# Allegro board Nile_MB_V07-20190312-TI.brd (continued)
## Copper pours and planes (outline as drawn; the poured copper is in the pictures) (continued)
GND on TOP (solid shape): 80.77,15.3 80.05,15.3 80.05,36.26 80.77,36.26
GND on TOP (solid shape): 80.79,14.53 58.83,14.53 58.83,15.27 80.79,15.27
GND on TOP (solid shape): 81.36,37.76 78.46,37.76 78.46,38.46 81.36,38.46
GND on TOP (solid shape): 81.86,30.41 81.16,30.41 81.16,38.46 81.86,38.46
GND on TOP (solid shape): 91.56,29.71 81.16,29.71 81.16,30.41 91.56,30.41
GND on TOP (solid shape): 92.26,45.66 78.46,45.66 78.46,46.36 92.26,46.36
GND on TOP (solid shape): 92.26,29.71 91.56,29.71 91.56,45.66 92.26,45.66
GND on TOP (solid shape): 76.6,28.97 76.47,28.84 76.47,27.89 75.93,27.89 75.93,29.48 76.6,29.48
GND on TOP (solid shape): 72.22,30.3 72.41,30.11 72.73,30.11 72.73,29.67 71.97,29.67 71.97,29.55 71.33,29.55 71.33,29.98 71.46,29.98 71.72,30.25 71.72,30.94 72.22,30.94
GND on BOTTOM (solid shape): 5.78,10.33 5.03,10.33 5.03,42.28 5.78,42.28
GND on BOTTOM (solid shape): 20.61,7.2 19.87,7.2 19.87,16.23 20.61,16.23
GND on BOTTOM (solid shape): 27.3,20.72 26.73,20.72 26.73,32.07 27.3,32.07
GND on BOTTOM (solid shape): 31.71,9.54 30.89,9.54 30.89,16.62 31.71,16.62
GND on BOTTOM (solid shape): 35,19.04 26.73,19.04 26.73,19.59 35,19.59
GND on BOTTOM (solid shape): 35.6,30.68 35.02,30.68 35.02,32.85 35.6,32.85
GND on BOTTOM (solid shape): 35.6,22.08 35.02,22.08 35.02,28.28 35.6,28.28
GND on BOTTOM (solid shape): 35.61,33.44 26.71,33.44 26.71,34.01 35.61,34.01
GND on BOTTOM (solid shape): 37.43,4.7 22.38,4.7 22.38,5.45 37.43,5.45
GND on BOTTOM (solid shape): 37.65,34.87 34.54,34.87 34.54,39.46 37.65,39.46
GND on BOTTOM (solid shape): 38.92,9.51 33.19,9.51 33.19,10.26 38.92,10.26
GND on BOTTOM (solid shape): 40.87,4.66 40.1,4.66 40.1,10.24 40.87,10.24
GND on BOTTOM (solid shape): 46.72,18.72 41.27,18.72 41.27,19.42 46.72,19.42
GND on BOTTOM (solid shape): 48.73,26.35 46.61,26.35 46.61,27.35 48.73,27.35
GND on BOTTOM (solid shape): 57.24,26.48 56.91,26.48 56.91,30.89 57.24,30.89
GND on BOTTOM (solid shape): 57.86,18.05 47.86,18.05 47.86,18.55 57.86,18.55
GND on BOTTOM (solid shape): 56.17,23.12 55.32,23.12 55.32,24.62 55.42,24.72 55.42,25.14 55.76,25.48 55.76,25.95 56.17,25.95
GND on BOTTOM (solid shape): 49.99,31.28 51.6,31.28 51.6,31.47 52.76,31.47 52.76,31.02 49.83,31.02 49.63,31.22 49.63,31.48 49.99,31.48
GND on BOTTOM (solid shape): 52.9,21.42 52.7,21.22 52.15,21.22 52.15,21.62 52,21.77 51.55,21.77 51.45,21.87 51.45,22.02 51.5,22.07 52.9,22.07
GND on BOTTOM (solid shape): 55.72,25.06 54.82,25.06 54.41,24.65 54.41,23.72 54.37,23.67 53.92,23.67 53.92,25.07 54.27,25.07 54.47,25.27 55.72,25.27
GND on BOTTOM (solid shape): 59.25,22.57 59.2,22.52 58.9,22.52 58.9,22.87 58.75,23.02 58.25,23.02 57.25,23.07 57.1,23.22 57.1,23.47 59.25,23.47
GND on BOTTOM (solid shape): 59.55,20.62 59.55,19.97 59.3,19.72 57.15,19.72 56.85,20.02 56.85,20.62 56.95,20.72 57.65,20.72 57.65,20.82 59.35,20.82
GND on BOTTOM (solid shape): 54.45,21.82 56.55,21.82 56.6,21.77 56.6,21.52 56.55,21.47 56.3,21.47 55.95,21.12 55.95,20.92 54.5,20.92 54.5,21.27 54.1,21.67 53.75,21.87 53.75,22.02 53.9,22.17 54.1,22.17
GND on BOTTOM (solid shape): 20.91,40.06 26.51,40.06 26.51,19.06 19.56,19.06 19.56,10.31 15.53,10.31 15.53,11.01 18.86,11.01 18.86,19.76 25.76,19.76 25.76,39.31 20.21,39.31 20.21,42.41 5.06,42.41 5.06,43.11 20.91,43.11
GND on INNER LAYER 7 (solid shape): 66.63,35.73 66.66,35.62 66.56,35.56 60.34,35.43 60.34,35.48 60.14,35.67 59.94,35.47 59.94,35.42 59.56,35.42 59.55,35.44 58.79,35.44 58.57,35.66 58.26,35.66 58.26,35.7 58.06,35.88 57.86,35.7 57.85,35.66 56.87,35.66 56.8,35.58 56.51,35.58 56.47,35.63 54.62,35.63 54.26,35.26 54.18,35.23 54.11,35.27 53.9,35.35 53.74,35.18 53.7,35.11 53.61,35.1 53.42,35.06 53.36,34.87 53.34,34.78 53.26,34.75 52.95,34.75 50.72,32.51 50.72,31.43 49.77,30.47 49.66,30.45 49.59,30.54 49.58,31.39 49.23,31.75 49.23,32.43 50.34,33.53 50.58,33.53 53.09,36.04 66.32,36.04
GND on INNER LAYER 7 (solid shape): outline of 706 points within 49.36,23.53 54.78,29.61
GND on INNER LAYER 9 (solid shape): 50.41,30.66 50.41,29.8 50.51,29.7 51.36,29.7 51.47,29.59 51.86,29.59 51.95,29.68 51.95,29.93 51.97,29.95 52.25,29.95 52.29,29.91 52.29,29.38 52.02,29.11 51.72,29.11 51.62,29.01 51.62,28.64 51.55,28.57 51.33,28.57 51.08,28.82 51.08,28.95 50.84,29.19 49.74,29.19 49.64,29.29 49.64,29.5 49.91,29.77 49.91,30.35 49.81,30.45 49.81,30.75 49.85,30.79 50.28,30.79
GND on TOP: outline of 146 points within 0.22,0.22 92.74,55.99 ; 12 cut-outs
GND on BOTTOM: outline of 146 points within 0.22,0.22 92.74,55.99 ; 15 cut-outs
GND on INNER LAYER 2: outline of 146 points within 0.22,0.22 92.74,55.99 ; 1 cut-out
GND on INNER LAYER 3: outline of 146 points within 0.22,0.22 92.74,55.99 ; 19 cut-outs
GND on INNER LAYER 4, INNER LAYER 9: outline of 146 points within 0.22,0.22 92.74,55.99
GND on INNER LAYER 5: outline of 146 points within 0.22,0.22 92.74,55.99 ; 7 cut-outs
GND on INNER LAYER 6: outline of 146 points within 0.22,0.22 92.74,55.99 ; 3 cut-outs
GND on INNER LAYER 7: outline of 146 points within 0.22,0.22 92.74,55.99 ; 1 cut-out
GND on INNER LAYER 8: outline of 146 points within 0.22,0.22 92.74,55.99 ; 5 cut-outs
V5P0_HUB on TOP (solid shape): 31.61,24.81 31.31,24.51 30.91,24.51 30.76,24.66 30.76,26.55 31.27,27.06 31.61,27.06
V5P0_HUB on INNER LAYER 3 (solid shape): 31.46,26.26 31.46,24.81 31.31,24.66 30.91,24.66 30.91,25.51 30.56,25.86 30.56,26.36 30.66,26.46 31.26,26.46
VBAT_EX on TOP (solid shape): 6.76,18.96 6.76,16.11 3.56,16.11 3.56,18.96 3.61,19.01 6.71,19.01
VBAT_EX on BOTTOM (solid shape): 66.32,15.11 66.32,14.55 66.18,14.41 64.79,14.41 64.79,15.17 64.99,15.37 66.06,15.37
VBAT_EX on BOTTOM (solid shape): 20.48,25.33 20.48,24.28 22.13,22.63 22.13,20.38 22.03,20.28 21.13,20.28 21.08,20.33 21.08,21.48 20.58,21.98 20.58,22.98 19.68,23.88 19.68,25.33 19.73,25.38 20.43,25.38
VBAT_EX on BOTTOM (solid shape): 45.44,37.4 45.44,35.29 45.19,35.04 44.25,35.04 43.5,34.29 42.8,34.29 42.8,35.31 43,35.51 43.87,35.51 44.15,35.79 44.15,36.14 44.24,36.23 44.53,36.23 44.73,36.43 44.73,37.47 45.37,37.47
VBAT_EX on BOTTOM (solid shape): 65.3,14.52 64.95,14.17 63.7,14.17 63.1,13.57 57.75,13.57 57.55,13.77 56.95,13.77 56.75,13.97 56.75,15.12 56.9,15.27 58.25,15.27 58.25,15.22 58.6,14.87 61.8,14.87 62.15,15.22 62.4,15.22 62.5,15.12 63.55,15.12 63.75,15.32 65.3,15.32
VBAT_EX on BOTTOM (solid shape): 57.38,16.83 57.38,14.03 57.18,13.83 56.74,13.83 56.18,13.27 56.18,12.88 54.22,11.39 49.54,11.32 42.65,13.48 40.53,13.48 40.48,13.43 40.33,13.43 40.18,13.58 40.18,15.78 40.28,15.88 43.56,15.88 45.04,14.95 50.36,13.36 51.23,13.2 53.59,13.12 55.35,14.04 55.5,14.14 55.5,14.37 55.47,14.87 55.53,15.54 55.55,15.77 55.58,16.31 55.87,17.02 57.18,17.03
VBAT_EX on INNER LAYER 3 (solid shape): outline of 316 points within 2.66,13.31 22.91,22.23
VBAT_EX on INNER LAYER 8 (solid shape): 43.75,34.42 43.74,32.57 42.69,32.57 42.69,34.61 43.47,34.66
VBAT_EX on INNER LAYER 8 (solid shape): 22.76,21.21 23.21,21.21 25.16,19.26 27.57,19.26 27.72,19.11 37.7,19.11 41.91,14.9 41.91,13.46 41.86,13.41 40.16,13.41 38.86,14.71 38.86,15.36 38.12,16.11 38.12,16.11 37.86,16.4 37.57,16.65 37.57,16.65 37.01,17.21 33.71,17.21 32.96,17.96 21.04,17.96 20.29,18.58 20.29,18.58 20.01,18.86 20.01,21.01 21.26,22.26 21.71,22.26
VBAT_EX on INNER LAYER 8 (solid shape): 61.15,15.39 61.22,15.35 61.24,15.27 61.5,14.94 61.76,15.27 61.78,15.35 61.86,15.39 66.59,15.39 66.63,15.35 67.24,15.35 67.48,15.11 67.48,14.14 67.33,13.98 65.65,13.98 65.39,14.24 65.05,14.24 64.73,13.92 64.7,13.92 64.34,13.93 64.3,13.58 64.3,13.47 64.21,13.42 56.57,13.42 56.28,13.95 56.28,13.99 56.22,14.05 56.15,14.17 56.1,14.18 56.02,14.25 55.25,14.25 54.58,14.31 54.58,15.09 54.64,15.15 56.39,15.15 56.56,15.14 56.7,15 56.7,14.9 57.24,14.36 57.87,14.36 58.05,14.54 59.3,14.54 59.33,14.47 59.35,14.44 59.69,14.38 59.8,14.71 59.76,14.78 60.37,15.39
VBAT_EX on INNER LAYER 9 (solid shape): 41.78,13.48 40.28,13.48 40.28,16.48 41.78,16.48
VBAT_EX on INNER LAYER 9 (solid shape): 43.63,32.43 42.63,32.43 42.63,34.73 43.63,34.73
VBAT_EX on INNER LAYER 9 (solid shape): 67.16,14.35 64.85,14.35 64.85,15.14 67.16,15.14
VBAT_EX on INNER LAYER 9 (solid shape): 22.11,22.06 22.11,21.66 22.56,21.21 23.11,21.21 23.86,20.46 23.86,19.91 24.76,19.01 34.56,19.01 34.56,18.26 34.21,17.91 31.26,17.91 31.16,18.01 23.16,18.01 21.21,19.96 21.21,22.21 21.26,22.26 21.91,22.26
VBATT on TOP (solid shape): 72.09,23 72.22,22.87 72.21,21.57 72.5,21.12 72.62,20.52 72.47,20.28 71.61,20.29 71.53,20.45 71.54,21.19 71.54,22.58 71.59,22.62 71.59,22.68 71.84,22.94 71.84,23.83 72.03,24.02 72.09,24.02
VBATT on BOTTOM (solid shape): 25.41,36.31 25.41,35.61 25.26,35.46 24.56,35.46 24.21,35.81 24.21,36.36 24.31,36.46 25.26,36.46
VBATT on BOTTOM (solid shape): 69.8,11.47 69.8,10.97 69.77,10.52 68.15,10.52 68.14,10.53 68.1,11.42 68.25,11.72 68.3,12.57 69.75,12.57
VBATT on BOTTOM (solid shape): 25.46,26.31 25.46,24.96 25.41,22.21 24.91,21.71 23.26,21.71 23.26,23.61 24.71,25.06 24.71,26.16 24.91,26.36 25.31,26.41
VBATT on BOTTOM (solid shape): 67.04,22.78 67.04,20.58 66.95,20.49 66.62,20.49 66.44,20.67 66.25,20.82 66.1,20.92 65.55,20.92 65.51,20.93 65.42,20.71 64.85,20.77 64.55,21.28 64.55,22.93 66.89,22.93
VBATT on INNER LAYER 8 (solid shape): 25.46,24.71 24.81,24.71 24.81,26.26 25.46,26.26
VBATT on INNER LAYER 8 (solid shape): 25.31,22.71 25.31,21.61 25.21,21.51 23.46,21.51 23.16,21.81 23.16,22.71 23.36,22.91 25.11,22.91
VBATT on INNER LAYER 8 (solid shape): outline of 906 points within 47.13,9.7 73.79,22.2
VBATT on INNER LAYER 9 (solid shape): 69.75,11.23 72.03,8.95 72.03,8.32 71.93,8.22 71.32,8.22 69.65,9.92 68.25,10.67 68.25,11.37 68.85,11.42 69.75,11.47
VBUS_OUT_5V on BOTTOM (solid shape): 10.16,41.61 10.16,40.01 9.96,39.81 8.01,39.81 7.96,39.86 7.96,41.71 10.06,41.71
VBUS_OUT_5V on BOTTOM (solid shape): 19.66,52.31 19.66,50.46 19.21,50.01 18.91,50.01 18.01,49.11 18.01,47.96 17.71,47.66 17.01,47.66 16.71,47.96 16.71,49.96 17.16,50.41 18.31,50.41 19.01,51.11 19.01,52.36 19.06,52.41 19.56,52.41
VBUS_OUT_5V on INNER LAYER 8 (solid shape): 10.16,41.66 10.16,40.46 9.51,39.81 7.96,39.81 7.96,41.71 10.11,41.71
VBUS_OUT_5V on INNER LAYER 8 (solid shape): 18.61,49.66 18.61,49.16 17.86,48.41 17.86,47.86 16.91,47.86 16.81,47.96 16.81,49.41 17.36,49.96 18.31,49.96
VDD13_BT on INNER LAYER 8 (solid shape): 23.7,9.57 23.7,8.77 23.5,8.57 23.5,7.82 23.4,7.72 21.4,7.72 21.3,7.82 21.3,8.42 23,8.42 23.15,8.57 23.15,8.82 23.23,9.01 23.15,9.2 23.15,9.37 23.45,9.67 23.6,9.67
VDD33_FEM on INNER LAYER 5 (solid shape): 24.4,12.71 24.4,12.19 24.38,12.18 24.3,12.02 24.38,11.86 24.4,11.84 24.4,11.15 24.26,11.01 24.2,10.78 24.28,10.56 24.39,10.46 24.4,9.38 24.29,9.3 24.15,9.03 24.25,8.75 24.33,8.7 24.4,8.67 24.8,8.27 28,8.27 28.8,9.07 28.8,9.12 29.02,9.33 29.02,10.18 28.8,10.39 28.8,10.42 27.95,11.27 27.95,11.72 28.05,11.82 28.85,11.82 29.67,11 29.67,8.53 27.8,6.67 27.5,6.67 27.49,6.69 27.25,6.83 27.02,6.69 27.01,6.67 25.56,6.67 25.5,6.73 24.83,6.73 24.78,6.68 24.4,6.68 23.9,7.18 23.89,7.18 23.35,7.72 23.35,9.83 23.38,9.86 23.4,9.91 23.5,10.02 23.5,10.15 23.6,10.24 23.6,11.39 23.57,11.42 23.57,11.99 23.5,12.05 23.5,12.17 23.09,12.58 23.09,13.13 23.21,13.26 23.85,13.26
VDD33_FEM on INNER LAYER 8 (solid shape): 24.65,7.62 24.59,7.56 24.59,7.18 24.81,6.96 24.81,6.67 24.53,6.39 24.53,6.2 24.26,6.2 24.16,6.3 24.16,6.71 24.29,6.84 24.29,7.05 23.89,7.45 23.89,7.97 23.99,8.07 24.65,8.07
VDD33_FEM on INNER LAYER 8 (solid shape): 26.97,9.64 27.03,9.64 27.14,9.53 27.14,8.28 27.07,8.21 27.06,8.21 26.84,8.02 26.95,7.77 26.94,7.6 26.81,7.51 26.66,7.53 26.47,7.71 26.38,7.78 26.36,7.81 26.36,8.2 26.59,8.43 26.6,8.43 26.67,8.64 26.7,8.85 26.7,8.99 26.71,8.99 26.72,9.16 26.79,9.32 26.7,9.48 26.7,9.56 26.81,9.67 26.94,9.67
VDD_CAP on BOTTOM (solid shape): 32.26,38.21 32.26,37.26 32.11,37.11 30.61,37.11 30.31,37.41 30.31,38.36 30.36,38.41 32.06,38.41
VDD_CAP on BOTTOM (solid shape): 46.96,34.71 46.96,33.99 46.77,33.8 46.39,33.8 46.1,33.51 46.1,32.93 45.83,32.66 45.26,32.66 45.18,32.74 45.18,34.23 45.51,34.56 45.51,34.91 46.76,34.91
VDD_CAP on BOTTOM (solid shape): 21.56,38.51 21.56,37.01 21.31,36.76 17.81,36.76 16.16,35.11 16.16,33.96 15.81,33.61 10.56,33.61 10.31,33.86 10.31,35.36 10.76,35.81 14.31,35.81 15.26,36.76 15.26,38.41 15.46,38.61 21.46,38.61
VDD_CAP on INNER LAYER 8 (solid shape): 32.36,38.61 32.36,37.26 32.06,36.96 30.46,36.96 29.26,38.16 24.79,38.16 24.72,38.24 22.64,38.24 21.54,37.14 21.54,37.06 17.81,37.06 17.61,37.26 17.61,38.61 17.66,38.66 20.16,38.66 21.46,39.96 31.01,39.96
VDD_CAP on INNER LAYER 8 (solid shape): outline of 150 points within 30.3,32.48 46.7,38.42
VDD_LCD_2P8 on BOTTOM (solid shape): 54.9,50.45 54.9,46.01 51.03,42.14 51.03,40.81 50.68,40.46 50.68,38.5 50.34,38.16 49.88,38.16 49.65,38.39 49.65,39.52 50.1,39.97 50.1,42.76 54.19,46.85 54.19,50.25 54.18,50.26 54.18,50.41 54.34,50.57 54.78,50.57
VIN_8V5 on BOTTOM (solid shape): 29.83,40.43 29.83,38.33 29.08,37.58 28.18,37.58 27.08,38.68 27.08,41.23 27.21,41.36 28.9,41.36
VIN_8V5 on INNER LAYER 8 (solid shape): 77.85,36.38 75.96,36.38 75.96,37.72 77.85,37.72
CAM2_VDD on BOTTOM (solid shape): 19.28,27.58 20.43,27.58 20.43,26.13 20.38,26.08 18.83,26.08 18.73,26.18 18.73,26.83 18.48,27.08 17.93,27.08 17.93,27.78 18.08,27.93 18.93,27.93
CAM2_VDD on INNER LAYER 8 (solid shape): 20.43,28.58 20.43,26.03 18.88,26.03 18.63,26.28 18.63,26.83 18.83,27.03 19.18,27.03 19.48,27.33 19.48,28.68 20.33,28.68
CAM_FRONT_1P8 on TOP (solid shape): 45.23,17.1 45.74,17.07 45.94,16.89 45.89,16.49 45.9,16.47 45.9,16.02 45.89,15.9 45.89,15.85 45.74,15.52 45.71,14.95 45.71,13.89 45.94,13.6 45.96,12.6 45.97,12.41 44.72,12.41 44.64,12.63 44.64,15.5 44.46,15.89 44.43,16.44 44.57,17.09 44.84,17.27
DC_5V on BOTTOM (solid shape): 74.19,47.73 74.19,45.17 73.73,44.71 72.71,44.71 72.28,44.28 72.28,44.27 71.85,43.84 71.84,43.84 71.8,43.8 71.8,42.33 71.7,42.23 68.28,42.23 67.94,42.57 67.94,44.43 68.28,44.77 70.25,44.77 70.58,45.1 70.58,45.81 72.71,47.94 73.98,47.94
DC_IN on BOTTOM (solid shape): 65.63,18.54 65.82,18.35 65.82,17.82 65.31,17.31 65.31,16.75 65.19,16.63 64.3,16.07 63.3,16.07 63.15,16.27 63.15,17.52 63.85,17.52 64,17.62 64.05,18.27 64.15,18.57 64.75,18.57
DC_IN on BOTTOM (solid shape): 72.15,41.42 72.15,38.17 72.5,37.82 72.5,33.62 72.25,33.37 71,33.37 70.7,33.67 70.7,35.02 70.75,35.07 71.35,35.07 71.55,35.27 71.55,36.72 71,37.27 70.6,37.27 70.5,37.37 70.5,38.02 70.35,38.17 68.2,38.17 68.15,38.22 68.15,39.32 69,39.32 69.5,39.82 69.5,40.52 69.15,40.87 69.15,41.12 69.8,41.77 71.8,41.77
DC_IN on INNER LAYER 9 (solid shape): 64.3,45.87 64.3,44.72 66.56,42.46 66.59,42.42 66.63,42.39 68.5,39.61 71.23,39.56 71.45,39.37 71.45,38.12 67.7,38.12 65.48,40.34 65.43,40.4 65.38,40.44 62.7,43.12 62.7,45.82 63.05,46.17 64,46.17
DC_IN on INNER LAYER 9 (solid shape): outline of 565 points within 63.44,15.34 82.83,39.32
SPK- on BOTTOM (solid shape): 68.68,6.02 68.68,5.64 69.18,5.14 69.6,5.14 69.6,4.32 69.58,4.3 69.05,4.3 68.89,4.46 68.89,4.7 68.56,5.03 67.89,5.03 67.63,5.29 67.63,5.72 68.01,6.1 68.6,6.1
USB_IN_MID on TOP (solid shape): 74.19,24.4 75.61,24.4 75.61,23.7 74.38,23.7 73.81,24.27 73.3,24.27 73.05,24.52 74.06,24.52
USB_IN_MID on TOP (solid shape): 76.13,23.75 76.36,23.75 76.64,23.47 76.65,22.22 76.74,21.67 76.66,21.63 76.54,21.59 76.39,21.62 76.33,21.62 76.26,21.63 76.02,21.7 75.97,23.06 75.36,23.67 75.36,24.07 75.53,24.24 75.64,24.24
USB_VBUS on TOP (solid shape): 75.13,25.08 75.58,25.08 75.76,25.08 76.21,25.08 76.22,25.07 76.35,25.02 76.4,25.02 76.5,24.92 76.6,24.72 76.9,24.47 77.25,24.17 77.55,23.87 77.87,23.87 79.3,23.82 79.55,23.57 79.55,22.82 77.84,22.86 76.93,22.86 76.76,23.03 76.76,23.54 76.68,23.62 76.68,23.63 76.5,23.81 76.41,23.81 76.4,23.83 76.21,23.83 75.69,24.34 75.69,24.47 75.58,24.47 75.39,24.66 73.8,24.68 73.64,24.74 73.33,24.72 73.14,24.86 73.14,25.03 73.67,25.04 73.94,25.01 74.15,25.12 75.13,25.12
V_LEDA on BOTTOM (solid shape): 36.64,42.11 36.64,40.24 36.61,40.21 35.62,40.21 35.49,40.34 35.49,40.89 35.12,41.26 34.34,41.26 34.35,41.26 34.21,41.26 34.19,41.28 34.19,42.17 34.38,42.36 36.39,42.36
V_LEDA on INNER LAYER 9 (solid shape): 42.08,50.39 42.08,48.68 39.86,46.46 39.86,42.76 38.42,41.32 34.31,41.32 34.09,41.54 34.09,42.57 34.56,42.91 34.96,42.91 37.51,42.81 37.61,42.86 37.86,43.11 38.01,43.56 38.21,43.96 38.26,46.91 41.63,50.49 41.98,50.49
VCOIN on INNER LAYER 9 (solid shape): 54.66,15.07 54.74,14.43 54.75,14.33 53.69,14.38 53.56,14.29 53.53,14.06 53.5,13.94 52.86,13.79 52.57,13.72 52.35,14.02 52.24,14.13 52.24,14.72 52.67,15.15 54.04,15.3 54.44,15.3
VCONN_IN on TOP (solid shape): 79.38,18.56 79.38,16.17 78.73,15.52 71.69,15.52 71.41,15.8 71.41,17.49 71.45,17.53 73.54,17.53 74.09,16.98 76.5,16.98 76.96,17.44 76.96,18.15 77.52,18.71 79.23,18.71
VCONN_IN on TOP (solid shape): 76.75,21.31 76.75,20.99 78.04,19.7 78.04,18.86 78.36,18.54 78.36,18.02 78.19,17.85 77.05,17.85 76.96,17.94 76.96,19.81 76.14,20.63 76.08,20.63 76.08,21.35 76.13,21.4 76.66,21.4
VCONN_IN on INNER LAYER 2 (solid shape): outline of 204 points within 70.01,16.08 73.78,23.42
VPH_PWR on TOP (solid shape): 68.66,27.7 68.66,26.94 68.54,26.94 68.41,27.06 68.41,27.38 67.97,27.83 67.58,27.83 67.58,28.33 68.03,28.33
VPH_PWR on TOP (solid shape): 67.91,26.96 67.91,25.9 68.09,25.72 68.09,25.31 68.05,25.27 67.42,25.27 67.36,25.33 67.36,26.88 67.57,27.09 67.78,27.09
VPH_PWR on TOP (solid shape): 72.6,23.13 73.3,22.43 73.77,22.43 74.38,21.81 74.38,20.46 73.62,20.46 73.62,20.46 72.35,21.72 72.35,23.95 72.47,24.08 72.6,24.08
VPH_PWR on TOP (solid shape): 68.55,24.24 68.55,23.38 68.37,23.2 68.33,23.2 68.25,23.12 68.25,22.84 68.13,22.72 67.69,22.72 67.35,23.06 67.35,24.21 67.46,24.32 68.47,24.32
VPH_PWR on TOP (solid shape): 74.41,21.77 74.41,20.47 74.4,20.46 74.4,20.2 75.02,19.58 75.01,19.06 75.22,18.92 76.02,18.94 76.35,18.83 76.38,17.75 76.32,17.22 75.55,17.18 74.89,17.19 74.28,17.19 74.09,17.38 74.09,17.56 73.48,18.17 73.01,18.17 72.87,18.31 72.87,18.79 73,18.92 73.54,18.92 73.76,19.14 73.76,19.81 73.49,20.08 73.06,20.08 73.01,20.13 73.01,21.59 72.89,21.71 73.2,22.02 74.16,22.02
VPH_PWR on BOTTOM (solid shape): 29.83,26.95 30.06,26.72 30.06,26.42 29.41,25.77 28.64,25.77 28.71,27.16 28.96,27.16
VPH_PWR on BOTTOM (solid shape): 30.05,24.19 30.05,23.93 29.7,23.58 29.68,23.57 28.66,23.57 28.66,24.82 29.43,24.82
VPH_PWR on BOTTOM (solid shape): 74.48,32.11 74.48,30.56 74.41,30.49 73.91,30.49 73.81,30.59 73.81,32.12 73.9,32.21 74.38,32.21
VPH_PWR on BOTTOM (solid shape): 23.52,17.49 23.52,17.02 23.46,16.96 23.05,16.96 22.69,16.6 22.69,16.24 22.07,16.24 22.02,16.29 22.02,17.06 22.58,17.62 23.39,17.62
VPH_PWR on BOTTOM (solid shape): 31.11,24.11 31.15,23.93 31.15,23.87 31.14,23.81 31.08,23.76 31.2,23.22 31.21,23.2 31.21,23.01 31.1,23.01 30.98,22.96 30.96,22.96 30.91,22.91 30.91,22.61 30.94,22.58 30.66,22.31 30.66,21.91 30.51,21.76 30.11,21.76 30.01,21.86 30.01,22.61 30.76,23.36 30.81,24.16
VPH_PWR on INNER LAYER 3 (solid shape): outline of 219 points within 19.88,15.33 33.58,28.73
VPH_PWR on INNER LAYER 3 (solid shape): outline of 1776 points within 21.63,4.1 76.39,19.36
VPH_PWR on INNER LAYER 5 (solid shape): outline of 386 points within 19.48,6 23.63,16.68
VPH_PWR on INNER LAYER 6 (solid shape): outline of 854 points within 67.2,15.29 76.62,28.59
VPH_PWR on INNER LAYER 8 (solid shape): 31.43,28.02 31.43,27.14 30.98,26.69 30.82,26.69 30.68,26.83 30.68,27.98 30.8,28.1 31.35,28.1
VPH_PWR on INNER LAYER 8 (solid shape): 29.34,27.13 29.34,26.17 29.44,26.07 29.44,25.94 29.12,25.62 29.12,24.18 29.59,23.71 29.59,23.59 29.48,23.48 28.79,23.48 28.55,23.72 28.55,23.89 28.44,24 28.29,24 28.26,24.03 28.26,27.22 28.43,27.39 29.08,27.39
VPH_PWR on INNER LAYER 8 (solid shape): 23.48,17.53 23.48,17.23 23.38,17.13 23.13,17.13 22.68,16.68 22.68,16.43 22.63,16.38 22.43,16.38 22.18,16.63 21.68,16.63 21.33,16.28 21.33,15.58 20.13,15.58 20.03,15.68 20.03,16.18 20.48,16.63 20.48,17.43 20.88,17.83 23.18,17.83
VPH_PWR on INNER LAYER 9 (solid shape): 29.23,26.86 29.23,26.23 29.45,26.01 29.45,25.74 29.42,25.71 28.71,25.71 28.6,25.82 28.6,26.82 28.71,26.93 29.16,26.93
VPH_PWR on INNER LAYER 9 (solid shape): 29.19,24.71 29.19,24.23 29.57,23.85 29.59,23.85 29.59,23.62 29.41,23.44 28.96,23.44 28.61,23.79 28.61,24.71 28.7,24.8 29.1,24.8
VPH_PWR on INNER LAYER 9 (solid shape): 31.06,24.26 31.09,24.23 31.09,23.77 31.04,23.46 31.1,23.22 31.21,23.11 31.21,22.96 31.16,22.96 31.01,22.81 31.01,22.66 30.66,22.31 30.66,22.26 30.66,22.25 30.64,22.16 30.66,22.07 30.66,22.06 30.66,21.96 30.51,21.81 30.11,21.81 29.96,21.96 29.96,22.31 30.01,22.36 30.01,22.36 30.66,23.01 30.69,23.04 30.69,23.84 30.71,23.86 30.71,23.94 30.72,23.96 30.76,24.06 30.72,24.16 30.71,24.18 30.71,24.41 30.76,24.46 30.88,24.46
VREG_5V on TOP (solid shape): 32.78,31.88 32.78,30.28 32.73,30.28 32.23,29.78 32.23,29.28 31.68,28.73 31.18,28.73 31.08,28.83 31.08,29.83 31.18,29.83 32.08,30.73 32.08,31.68 32.33,31.93 32.73,31.93
VREG_5V on BOTTOM (solid shape): 72.52,16.15 72.52,14.3 71.47,14.3 71.42,14.35 71.42,16.26 71.43,16.27 72.4,16.27
VREG_5V on BOTTOM (solid shape): 19.86,39.71 19.86,39.11 19.76,39.01 17.16,39.01 16.96,39.21 16.96,39.86 17.11,40.01 19.56,40.01
VREG_5V on BOTTOM (solid shape): 74.5,18.55 74.5,17.65 74.04,17.19 74.04,16.56 72.61,15.13 72.61,13.75 72.62,13.74 72.59,13.71 72.19,13.71 71.87,14.03 71.87,16.12 72.15,16.4 72.91,16.4 73.6,17.09 73.6,18.35 73.86,18.61 74.44,18.61
VREG_5V on INNER LAYER 8 (solid shape): 19.86,39.81 19.86,39.16 19.71,39.01 18.36,39.01 18.31,39.06 18.31,39.86 18.36,39.91 19.76,39.91
VREG_L1A_0P8 on INNER LAYER 7 (solid shape): 50.95,23.45 51.18,23.32 51.41,23.45 52.33,23.45 52.38,23.4 52.41,23.36 52.43,23.33 52.43,23.03 52.41,23.01 52.34,22.96 52.29,22.88 52.28,22.87 52.17,22.76 51.85,22.76 51.69,22.83 51.53,22.8 51.51,22.79 50.57,22.79 50.44,22.92 50.44,23.31 50.58,23.45
VREG_L2A_1P2 on TOP (solid shape): 76.59,30.23 76.59,29.74 76.49,29.64 75.86,29.64 75.58,29.36 75.58,29.02 75.51,28.95 75.3,28.95 75.11,29.14 75.11,30 75.37,30.26 76.18,30.26 76.31,30.39 76.43,30.39
VREG_L2A_1P2 on INNER LAYER 2 (solid shape): 76.86,30.29 76.86,29.75 76.3,29.19 75.79,29.19 74.82,28.22 74.82,27.6 74.57,27.35 74.09,27.35 73.99,27.45 73.99,27.57 74.38,27.96 74.38,28.72 75.86,30.2 76.16,30.2 76.34,30.38 76.77,30.38
VREG_L2A_1P2 on INNER LAYER 7 (solid shape): outline of 1387 points within 49.6,26.31 76.66,35.58
VREG_L7A_0P8 on INNER LAYER 3 (solid shape): 55.04,29.52 55.04,29.51 55.18,29.34 55.4,29.34 55.41,29.34 55.47,29.34 55.54,29.28 55.64,29.26 55.67,29.24 55.69,29.21 55.7,29.14 55.74,29.09 55.83,29 55.83,28.96 55.83,28.71 55.44,28.71 55.2,28.95 55.2,28.95 55.17,28.99 54.81,28.99 54.77,29.03 54.76,29.04 54.72,29.12 54.65,29.18 54.62,29.2 54.62,29.28 54.59,29.31 54.59,29.54 54.69,29.64 54.91,29.64
VREG_L7A_0P8 on INNER LAYER 8 (solid shape): 55.03,29.57 55.03,29.55 55.15,29.36 55.38,29.33 55.38,29.33 55.5,29.33 55.6,29.28 55.7,29.29 55.73,29.3 55.84,29.19 55.84,29.1 55.84,29.09 55.83,29.01 55.84,28.93 55.84,28.92 55.84,28.78 55.8,28.74 55.28,28.74 55.26,28.76 55.12,28.94 54.88,28.95 54.82,28.97 54.82,28.98 54.71,29.15 54.52,29.22 54.5,29.22 54.34,29.38 54.34,29.41 54.31,29.56 54.2,29.67 54.2,29.91 54.24,29.95 54.64,29.95
VREG_L8A_1P8 on INNER LAYER 6 (solid shape): 71.38,29.44 71.77,29.05 72.3,29.05 72.3,28.6 72.28,28.58 71.49,28.58 70.91,29.16 70.91,29.38 70.99,29.46 71.38,29.46
VREG_L10A_1P8_RES on INNER LAYER 8 (solid shape): 57.26,30.76 57.44,30.67 57.63,30.74 57.67,30.75 57.7,30.73 57.77,30.66 57.97,30.47 57.98,30.27 57.89,30 57.78,29.86 57.46,29.83 57.39,30.03 57.16,30.26 56.67,30.28 56.61,30.36 56.6,30.43 56.56,30.47 56.61,30.49 56.61,30.57 56.61,30.64 56.73,30.76
VREG_L13A_1P8 on BOTTOM (solid shape): 42.53,28.18 42.53,26.23 42.43,26.13 41.93,26.13 41.83,26.23 41.83,28.33 41.93,28.43 42.28,28.43
VREG_L13A_1P8 on INNER LAYER 5 (solid shape): 55.45,30.81 55.58,30.66 55.77,30.69 55.81,30.72 56.01,30.51 56.01,30.08 55.96,30.03 55.68,30.03 55.49,30.22 54.58,30.22 54.55,30.19 52.3,30.19 51.96,30.13 51.4,29.52 51.36,29.25 51.03,29.25 50.92,29.36 50.92,30.03 51.74,30.85 55.44,30.85
VREG_L13A_1P8 on INNER LAYER 5 (solid shape): 47.2,34.45 47.28,34.45 47.54,34.18 47.54,33.9 47.4,33.76 46.77,33.76 46.53,33.9 46.3,33.76 46.24,33.76 45.22,32.74 40.1,32.74 38.96,33.88 38.96,34.49 39,34.53 40.1,34.53 40.47,34.16 40.47,34.09 41.37,34.09 41.54,34.26 41.56,34.26 41.66,34.31 41.73,34.4 41.74,34.44 42.5,34.44 43.39,33.55 44.42,33.55 45.45,34.58 47.07,34.58
VREG_L13A_1P8 on INNER LAYER 5 (solid shape): outline of 421 points within 60.76,25.66 78.26,29.3
VREG_L13A_1P8 on INNER LAYER 8 (solid shape): 50.2,28.82 50.2,28.56 50.13,28.49 49.66,28.49 48.77,27.6 48.76,27.59 48.59,27.59 48.58,27.6 48.51,27.61 48.45,27.6 48.44,27.59 48.37,27.59 48.32,27.64 48.32,27.83 48.37,27.88 48.48,27.88 48.48,27.89 49.49,28.9 50.12,28.9
VREG_L13A_1P8 on INNER LAYER 8 (solid shape): 51.39,29.6 51.39,29.33 51.35,29.32 51.3,29.3 51.25,29.27 51.23,29.26 51.18,29.26 51.17,29.26 51.09,29.28 51.01,29.26 51,29.26 50.83,29.26 50.8,29.22 50.78,29.22 50.57,29.12 50.52,28.91 50.59,28.77 50.72,28.7 50.86,28.64 51,28.68 51.02,28.68 51.12,28.68 51.18,28.66 51.23,28.66 51.25,28.59 51.3,28.54 51.32,28.52 51.32,28.29 51.27,28.24 50.92,28.24 50.76,28.4 50.76,28.41 50.67,28.41 50.54,28.44 50.44,28.41 50.43,28.41 49.43,28.41 49.43,28.83 50.29,29.69 51.3,29.69
VREG_L13A_1P8 on INNER LAYER 8 (solid shape): outline of 201 points within 41.39,27.66 49.55,34.55
VREG_L19A_3P0 on BOTTOM (solid shape): 39.75,39.15 39.75,36.2 39.21,35.66 39.21,33.67 39.23,33.41 39.19,32.85 39.13,32.82 37.8,32.83 37.87,35.99 38.41,36.53 38.41,39.07 38.77,39.43 39.47,39.43
VREG_L19A_3P0 on INNER LAYER 3 (solid shape): 37.63,27.62 38.16,27.09 38.16,25.97 38.03,25.84 37.42,25.84 37.18,26.08 37.18,27.68 37.32,27.82 37.63,27.82
VREG_L19A_3P0 on INNER LAYER 8 (solid shape): 40.4,38.28 38.55,38.28 38.55,39.63 40.4,39.63
VREG_L19A_3P0 on INNER LAYER 9 (solid shape): 39.04,33.43 39.21,33.33 39.25,33.06 39.25,29.26 38.49,28.3 38.49,26.58 38.12,25.69 37.32,25.69 37.2,25.81 36.85,26.29 36.83,27.82 37.3,27.82 37.3,27.78 37.31,27.74 37.33,27.71 37.36,27.67 37.39,27.65 37.43,27.63 37.47,27.62 37.51,27.62 37.55,27.63 37.58,27.64 37.62,27.66 37.65,27.69 37.67,27.72 37.69,27.76 37.7,27.8 37.7,27.84 37.69,27.88 37.67,27.92 37.65,27.95 37.62,27.98 37.58,28 37.55,28.01 37.51,28.02 37.47,28.02 37.43,28.01 37.39,27.99 37.36,27.97 37.33,27.93 37.31,27.9 37.3,27.86 37.3,27.82 36.83,27.82 36.81,29.13 37.84,30.15 37.82,33.32 37.84,33.45 38.32,33.45
VREG_S1A_0P752 on TOP (solid shape): 64.36,24.05 64.36,22.73 64.21,22.58 62.81,22.58 62.51,22.88 62.51,24.49 62.74,24.72 63.69,24.72
VREG_S1A_0P752 on BOTTOM (solid shape): 63.63,24.71 63.63,23.15 63.5,22.67 60.85,22.37 60.35,22.22 60.05,24.8 60.5,24.72 62.2,24.77 62.45,24.82 63.15,24.82 63.45,24.87
VREG_S1A_0P752_GOLD on BOTTOM (solid shape): 57.03,25.84 57.03,25.13 57.08,25.08 59.39,25.06 59.49,24.86 60.55,24.81 60.58,23.76 60.48,23.66 59.42,23.66 59.31,23.76 57.03,23.76 56.93,23.66 56.93,23.1 56.52,23.1 56.47,23.15 56.47,25.84 56.57,25.94 56.93,25.94
VREG_S1A_0P752_GOLD on INNER LAYER 3 (solid shape): 56.53,25.8 56.63,25.78 56.72,25.8 56.73,25.8 56.95,25.8 56.98,25.77 56.98,25.64 56.92,25.47 56.98,25.3 56.98,25.14 56.92,24.97 56.98,24.8 56.98,24.63 56.98,24.62 56.94,24.48 56.98,24.34 56.98,24.33 56.98,24.15 56.98,24.13 56.94,24 56.98,23.86 56.98,23.84 56.98,23.52 56.89,23.43 56.53,23.43 56.03,23.93 56.03,24.07 56.22,24.26 56.34,24.44 56.28,24.65 56.28,24.81 56.34,24.98 56.28,25.14 56.28,25.31 56.34,25.47 56.28,25.63 56.27,25.65 56.27,25.75 56.32,25.8 56.53,25.8
VREG_S1A_0P752_GOLD on INNER LAYER 8 (solid shape): outline of 224 points within 56.01,23.24 59.6,25.81
VREG_S1A_0P752_SILVER on BOTTOM (solid shape): 54.94,24.57 54.94,24.57 54.94,23.15 55.1,23 57.96,22.94 58.11,22.37 58.61,22.34 59.01,22.32 59.28,22.35 59.37,22.55 59.43,23.77 61.07,23.8 61.07,23.36 60.57,23.03 60.56,21.4 60.33,21.01 59.23,21.04 57.04,20.93 56.81,21.23 56.83,21.87 56.72,22.13 54.39,22.13 54.18,22.34 54.18,22.84 54.54,23.2 54.54,24.54 54.74,24.75 54.94,24.75
VREG_S1A_0P752_SILVER on INNER LAYER 3 (solid shape): outline of 82 points within 54.51,22.36 57.02,25.58
VREG_S1A_0P752_SILVER on INNER LAYER 8 (solid shape): 55.54,25.23 55.58,25.19 55.62,25.16 55.65,25.15 55.65,25.05 55.63,25 55.62,24.96 55.6,24.93 55.49,24.87 55.44,24.78 55.44,24.77 55.3,24.63 55.3,24.27 55.3,24.26 55.26,24.16 55.3,24.06 55.3,24.04 55.3,23.75 55.3,23.72 55.3,23.69 55.3,23.42 55.9,22.82 56.02,22.82 56.03,22.82 56.14,22.79 56.24,22.82 56.25,22.82 56.51,22.82 56.52,22.82 56.63,22.79 56.74,22.82 56.75,22.82 57.04,22.82 57.06,22.81 57.14,22.78 57.24,22.78 57.26,22.78 57.53,22.51 57.53,22.04 57.41,21.92 54.71,21.92 54.52,22.11 54.52,22.16 54.25,22.43 54.25,22.56 54.3,22.6 54.47,22.6 54.65,22.54 54.82,22.62 54.85,22.64 54.9,22.82 54.83,22.99 54.83,23.09 54.71,23.21 54.72,23.24 54.72,23.36 54.66,23.46 54.66,24.01 54.63,24.04 54.63,24.7 54.68,24.74 54.71,24.8 54.71,24.81 55.12,25.21 55.14,25.21 55.2,25.22 55.26,25.25 55.53,25.25
VREG_S1A_0P752_SILVER on INNER LAYER 9 (solid shape): 56.52,22.42 56.52,22.23 56.39,22.1 54.42,22.1 54.24,22.28 54.24,22.58 54.67,22.58 54.98,22.89 56.05,22.89
VREG_S1C_S4C_0P752 on BOTTOM (solid shape): 56.6,28.87 56.6,28.32 56.62,28.3 56.62,27.32 56.75,27.2 56.75,26.75 56.66,26.66 56.28,26.66 56.28,27.3 56.16,27.42 56.16,28.87 56.2,28.92 56.55,28.92
VREG_S1C_S4C_0P752 on BOTTOM (solid shape): 46.96,23.26 46.96,21.76 45.96,20.76 42.31,20.76 41.31,19.76 28.11,19.76 28.01,19.86 28.01,21.51 34.21,21.51 34.61,21.91 41.46,21.91 42.46,22.91 45.16,22.91 45.36,23.11 45.36,23.36 45.56,23.56 46.66,23.56
VREG_S1C_S4C_0P752 on BOTTOM (solid shape): 53.91,28.53 53.91,26.81 53.75,26.66 53.11,26.66 53.07,26.61 53.07,25.81 52.65,25.38 52.65,24.35 52.43,24.13 52.02,24.13 51.98,24.17 51.98,26.36 51.93,26.42 50.1,26.42 49.94,26.26 49.94,25.34 49.07,24.46 47.79,24.46 47.64,24.31 47.64,23.3 47.39,22.96 47.39,21.97 47.06,21.65 47.06,20.86 45.25,20.86 45.25,21.21 45.86,22.04 45.87,24.92 45.4,25.41 45.42,25.8 45.68,26.14 48.85,26.15 48.94,26.24 48.94,27.18 49.16,27.41 53.14,27.41 53.19,27.46 53.19,27.9 53.31,28.02 53.31,28.22 53.68,28.58 53.85,28.58
VREG_S1C_S4C_0P752 on INNER LAYER 2 (solid shape): 56.69,28.74 56.69,28.71 56.69,28.65 56.72,28.59 56.72,28.58 56.72,28.3 56.72,28.29 56.69,28.19 56.72,28.1 56.72,28.08 56.72,28.02 56.97,27.77 57,27.77 57,26.57 56.99,26.56 56.78,26.35 56.48,26.35 56.03,26.8 56.03,26.98 56.24,27.19 56.24,28.78 56.65,28.78
VREG_S1C_S4C_0P752 on INNER LAYER 2 (solid shape): 54.26,28.97 54.26,28.75 54.26,28.74 54.24,28.68 54.26,28.61 54.26,28.6 54.26,28.28 54.26,28.27 54.24,28.19 54.26,28.11 54.26,28.1 54.26,27.84 54.16,27.74 54.16,26.65 54.27,26.54 54.27,26.4 54.22,26.35 54,26.35 53.95,26.37 53.8,26.52 53.45,26.52 53.28,26.35 53.01,26.35 53,26.36 52.81,26.34 52.76,26.16 52.76,26.15 52.76,25.78 52.75,25.72 52.76,25.66 52.76,25.28 52.75,25.22 52.76,25.16 52.76,24.79 52.75,24.73 52.76,24.67 52.76,24.29 52.75,24.23 52.76,24.17 52.76,23.91 52.69,23.84 52.55,23.84 52.42,23.9 52.29,23.84 52.27,23.84 52.05,24.06 52.05,24.13 52.06,24.14 52.09,24.23 52.06,24.32 52.05,24.34 52.05,24.62 52.06,24.64 52.09,24.73 52.06,24.82 52.05,24.83 52.05,25.07 52.21,25.23 52.21,26.47 52.09,26.59 51.84,26.59 51.79,26.64 51.79,27.31 52.27,27.29 52.57,27.42 53.41,27.41 53.66,27.66 53.66,28.71 53.94,28.99 54.24,28.99
VREG_S1C_S4C_0P752 on INNER LAYER 3 (solid shape): 56.83,28.46 56.85,28.4 56.9,28.31 57,28.27 57.02,28.27 57.06,28.22 57.06,27.72 56.95,27.61 56.95,27.57 56.95,27.56 56.95,27.34 57.1,27.19 57.11,27.19 57.16,27.14 57.16,26.73 57.16,26.68 57.14,26.65 57.11,26.64 57.01,26.59 56.92,26.44 56.86,26.41 56.81,26.4 56.76,26.38 56.71,26.34 56.55,26.34 56.49,26.38 56.46,26.4 56.4,26.41 56.18,26.63 56.18,26.65 56.13,26.78 56.02,26.86 55.99,26.88 55.99,27.03 56.03,27.06 56.27,27.3 56.27,27.34 56.28,27.36 56.3,27.38 56.3,28.04 56.29,28.06 56.22,28.18 56.11,28.25 56.09,28.25 56.01,28.33 56.01,28.57 56.22,28.78 56.26,28.8 56.29,28.83 56.45,28.83
VREG_S1C_S4C_0P752 on INNER LAYER 3 (solid shape): outline of 113 points within 51.76,23.86 54.28,29.01
VREG_S1C_S4C_0P752 on INNER LAYER 5 (solid shape): outline of 514 points within 52.01,23.95 57.19,28.69
VREG_S1C_S4C_0P752 on INNER LAYER 8 (solid shape): 56.5,28.95 56.54,28.92 56.6,28.89 56.65,28.85 56.67,28.78 56.67,28.68 56.71,28.59 56.71,28.48 57.06,28.13 57.06,27.99 56.91,27.84 56.91,27.82 56.9,27.81 56.85,27.68 56.91,27.55 56.91,27.41 56.93,27.39 56.93,27.38 57,27.26 57.11,27.19 57.11,27.09 57.17,27.01 57.17,26.7 57.12,26.64 56.29,26.64 56.24,26.69 56.24,27.07 56.25,27.08 56.26,27.15 56.25,27.22 56.24,27.23 56.24,27.29 56.25,27.31 56.3,27.46 56.24,27.62 56.24,27.83 56.3,28.03 56.18,28.21 56,28.39 55.99,28.39 55.99,28.58 56.17,28.75 56.18,28.76 56.29,28.83 56.35,28.93 56.36,28.95
VREG_S1C_S4C_0P752 on INNER LAYER 8 (solid shape): 54.13,28.71 54.2,28.69 54.23,28.62 54.27,28.55 54.33,28.49 54.33,28.43 54.34,28.36 54.27,28.31 54.23,28.23 54.23,28.21 54.11,28.1 54.11,27.78 54.22,27.68 54.22,27.66 54.26,27.59 54.33,27.54 54.32,27.46 54.33,27.37 54.28,27.33 54.24,27.28 54.23,27.25 54.13,27.25 53.98,27.1 53.98,27.08 53.95,27 53.95,26.92 53.95,26.9 53.71,26.66 53.41,26.66 52.76,26.01 52.76,24.18 52.73,24.14 52.73,24.05 52.68,24.01 52.1,24.01 51.96,24.15 51.96,24.62 51.97,24.66 51.96,24.71 51.96,24.84 51.97,24.85 52,24.98 51.97,25.1 51.96,25.11 51.96,25.82 51.97,25.83 52.01,25.97 51.97,26.1 51.96,26.11 51.96,26.42 51.73,26.65 51.73,27.06 51.84,27.17 52.27,27.17 52.42,27.32 52.42,27.43 52.54,27.55 52.59,27.57 52.74,27.57 52.77,27.54 52.89,27.54 53.01,27.57 53.08,27.67 53.27,27.67 53.3,27.69 53.31,27.69 53.5,27.87 53.45,28.12 53.45,28.62 53.54,28.71
VREG_S1C_S4C_0P752 on INNER LAYER 9 (solid shape): 56.73,26.72 56.14,26.72 56.14,26.98 56.17,27 56.26,27.15 56.17,27.31 56.14,27.32 56.14,28.94 56.73,28.94
VREG_S1C_S4C_0P752 on INNER LAYER 9 (solid shape): 54.03,28.44 54.02,28.41 54.02,28.33 54.05,28.26 54.06,28.25 54.06,27.05 53.32,26.31 53.27,26.27 53.23,26.21 53.08,26.07 53.08,25.69 53.05,25.66 53.03,25.61 52.79,25.38 52.79,24.41 52.46,24.08 52.05,24.08 51.95,24.18 51.95,24.59 51.96,24.6 51.97,24.66 51.96,24.73 51.95,24.74 51.95,26.22 51.76,26.41 50.35,26.41 49.76,25.82 49.76,25.33 49.01,24.58 47.73,24.58 47.68,24.53 47.68,23.12 45.97,23.12 45.96,23.13 45.96,24.12 46.5,24.66 46.5,25.26 46.95,25.71 47.86,25.71 49.54,27.39 52.95,27.39 53.26,27.7 53.26,28.43 53.44,28.61 53.85,28.61
VREG_S2A_0P8 on TOP (solid shape): 65.67,20.2 65.67,19.39 64.63,18.35 63.15,18.35 62.64,18.86 62.64,20.38 62.84,20.58 65.29,20.58
VREG_S2A_0P8 on BOTTOM (solid shape): 55.48,28.7 55.58,28.69 55.8,28.67 55.97,28.54 55.95,27.91 55.44,27.84 55.38,27.74 55.38,26.84 55.2,26.6 55.19,26.6 55.02,26.43 55.02,25.56 54.52,25.56 54.42,25.37 54.33,25.28 53.88,25.28 53.69,25.1 53.69,24.1 53.82,23.97 53.82,23.02 53.67,22.87 53.67,20.62 53.03,19.99 51.19,19.99 50.77,20.38 50.77,22.37 50.77,22.37 50.77,23.72 50.97,23.92 51.22,23.92 51.32,23.82 51.32,23.12 51.27,23.07 51.27,22.87 51.26,22.86 51.26,22.42 51.27,22.42 51.27,21.92 51.34,21.85 51.34,21.2 51.51,21.03 52.82,21.03 53.09,21.3 53.09,22.34 52.57,22.36 52.57,24.02 52.77,24.22 52.77,25.32 53.37,25.92 53.76,25.92 53.83,25.98 53.83,26.53 54.17,26.87 54.42,26.87 54.73,27.18 54.73,28.44 54.73,28.52 54.78,28.57 54.83,28.6 54.99,28.66 55.14,28.69 55.42,28.71
VREG_S2A_0P8 on INNER LAYER 2 (solid shape): 64.5,20.44 64.5,18.77 64.11,18.38 63.27,18.38 62.96,18.69 62.96,20.05 63.42,20.51 64.43,20.51
VREG_S2A_0P8 on INNER LAYER 3 (solid shape): 64.46,20.47 64.46,19.4 64.13,19.07 64.13,18.53 63.77,18.17 62.93,18.17 62.61,18.49 62.61,19.92 62.62,19.93 62.8,19.93 63.03,19.7 63.54,19.7 63.79,19.95 63.79,20.53 64.4,20.53
VREG_S2A_0P8 on INNER LAYER 3 (solid shape): 51.54,24.76 51.54,24.16 51.48,23.99 51.54,23.81 51.54,23.11 50.94,23.11 50.83,23.22 50.83,23.39 50.84,23.4 50.87,23.49 50.84,23.58 50.83,23.59 50.83,23.83 50.88,23.87 50.9,23.87 50.95,23.88 51.01,23.9 51.05,23.9 51.11,23.96 51.11,23.99 51.12,24 51.14,24.24 50.97,24.4 50.96,24.4 50.89,24.46 50.88,24.53 50.86,24.58 50.86,24.83 51.47,24.83
VREG_S2A_0P8 on INNER LAYER 3 (solid shape): outline of 138 points within 53.03,23.14 55.78,28.91
VREG_S2A_0P8 on INNER LAYER 7 (solid shape): outline of 1474 points within 50.95,17.67 63.77,29.01
VREG_S2A_0P8 on INNER LAYER 8 (solid shape): 51.36,24.7 51.36,24.69 51.4,24.63 51.45,24.59 51.44,24.53 51.45,24.47 51.45,24.46 51.45,23.86 51.39,23.73 51.44,23.59 51.41,23.49 51.44,23.39 51.45,23.38 51.45,23.24 51.45,23.23 51.44,23.17 51.45,23.11 51.45,23.1 51.45,23.01 51.41,22.97 51.01,22.97 50.75,23.23 50.75,23.79 50.84,23.88 50.87,23.88 51.15,24.06 51.02,24.37 50.99,24.39 50.99,24.58 51.14,24.73 51.32,24.73
VREG_S2A_0P8 on INNER LAYER 8 (solid shape): outline of 124 points within 52.8,23.13 55.72,28.75
VREG_S2C_1P125 on TOP (solid shape): 43.9,34.64 43.87,34.6 43.87,34.12 42.85,33.09 42.78,32.97 42.8,32.84 42.8,32.83 42.8,32.33 42.8,32.26 42.18,32.26 42.18,33.04 42.62,33.49 42.62,34.42 42.7,34.42 42.7,34.41 42.83,34.41 42.83,34.42 43.49,34.42 43.49,34.69 43.87,34.69
VREG_S2C_1P125 on TOP (solid shape): outline of 87 points within 40.35,17.66 42.77,34.71
VREG_S2C_1P125 on INNER LAYER 3 (solid shape): 41.45,27.83 41.45,27.58 41.42,27.55 41.42,27.28 41.33,27.19 41.04,27.19 40.81,27.42 39.79,27.42 39.49,27.72 39.02,27.72 39.02,27.94 39.12,28.04 41.24,28.04
VREG_S2C_1P125 on INNER LAYER 8 (solid shape): 41.07,28.91 41.07,27.97 41.4,27.64 42.28,27.64 42.37,27.72 42.63,27.72 43.34,28.43 45.45,28.43 45.45,27.53 45.41,27.49 45.02,27.49 44.97,27.5 44.93,27.49 44.66,27.49 44.65,27.51 44.48,27.6 44.32,27.51 44.3,27.49 44.09,27.49 44.09,27.73 44.06,27.75 44.04,27.8 44.02,27.84 43.75,27.95 43.54,27.75 43.49,27.68 43.4,27.68 43.23,27.7 43.09,27.62 43.02,27.49 43.04,27.34 43.05,27.31 42.92,27.12 42.72,27.03 42.64,27.02 41.31,27.02 41.21,27.12 40.96,27.12 40.83,27 40.05,27 38.71,28.34 38.31,28.61 37.56,29.16 36.06,30.66 33.46,30.72 33.44,30.74 33.28,30.84 33.1,30.75 33.09,30.73 30.64,30.78 29.51,30.78 29.41,30.88 29.41,31.51 29.71,31.81 29.71,32.1 30.16,32.46 37.52,32.46
VREG_S2C_1P125 on INNER LAYER 8 (solid shape): outline of 119 points within 40.07,23.87 50.56,26.2
VREG_S2C_1P125 on BOTTOM: 28.63,29.55 28.63,31.26 29.01,31.64 32.6,31.64 32.81,31.43 32.81,30.77 32.62,30.58 30.85,30.58 30.41,30.14 30.41,29.45 28.73,29.45
VREG_S3A_0P6 on TOP (solid shape): 67.44,21.4 67.44,17.76 67.17,17.49 66.13,17.49 65.97,17.65 65.97,19.03 66.19,19.25 66.19,21.39 66.28,21.48 67.36,21.48
VREG_S3A_0P6 on TOP (solid shape): 43.47,20.04 43.68,20.05 43.68,19.27 44.24,18.71 44.24,17.68 44.19,17.63 43.4,17.63 42.73,17.64 42.73,18 42.9,18.13 42.9,18.97 42.91,20.05 43.21,20.05
VREG_S3A_0P6 on BOTTOM (solid shape): 51.25,26.19 51.25,24.97 51.11,24.83 51,24.83 50.6,24.43 50.6,24.13 50.33,23.86 50.33,23.23 49.82,22.72 49.82,22.08 49.36,21.62 49.4,20.99 49.82,20.79 49.79,19.91 49.52,19.9 49.39,19.91 48.74,20.35 48.61,20.47 48.51,20.58 48.48,20.64 48.48,22.76 49.18,23.46 49.18,24.25 49.99,25.06 50.4,25.06 50.57,25.23 50.57,26.23 50.63,26.29 51.15,26.29
VREG_S3A_0P6 on INNER LAYER 8 (solid shape): outline of 1156 points within 48.2,15.14 67.21,26.29
VREG_S3C_0P752 on BOTTOM (solid shape): 44.36,30.66 44.86,30.66 45.36,30.16 46.61,30.16 46.66,30.11 46.66,28.11 46.46,28.11 46.26,28.31 43.21,28.31 42.76,28.76 31.61,28.76 31.36,29.01 31.36,30.16 31.41,30.21 35.91,30.21 36.76,31.06 43.96,31.06
VREG_S3C_0P752 on BOTTOM (solid shape): 52.39,30.53 52.39,30.5 52.44,30.45 52.57,30.45 52.72,30.38 52.73,29.7 52.83,29.49 52.86,29.43 52.89,29.25 52.83,29.19 52.83,28.89 52.88,28.84 52.9,28.84 52.9,28.61 53.14,28.43 53.17,28.28 53.12,28.13 50.92,28.1 50.8,28.06 50.71,28.05 50.49,28.03 50.29,28.02 50.18,28.03 50,28.03 49.91,28.08 49.9,28.1 46.61,28.09 46.1,29.68 49.55,29.68 49.55,29.13 52.25,29.13 52.25,29.68 52.24,29.68 52.24,29.73 50.54,29.73 50.54,29.68 50.42,29.68 50.42,29.73 49.92,29.73 49.92,29.68 46.1,29.68 45.98,30.07 45.97,30.11 45.98,30.13 45.99,30.16 46.01,30.18 46.03,30.19 46.07,30.2 49.23,30.2 49.55,30.18 49.74,30.22 50.61,30.64 52.16,30.64
VREG_S3C_0P752 on INNER LAYER 2 (solid shape): 52.29,29.5 52.29,29.49 52.29,29.31 52.26,29.23 52.26,29.14 52.26,29.1 52.31,29.05 52.31,28.81 52.26,28.69 52.31,28.56 52.31,28.27 52.31,28.25 52.28,28.17 52.31,28.08 52.31,28.07 52.31,27.91 52.2,27.82 52.18,27.71 52.23,27.55 52.25,27.41 52.03,27.41 51.84,27.58 51.74,27.68 51.74,28.7 51.59,28.85 51.57,28.85 51.57,29.07 51.99,29.49 52.04,29.51 52.06,29.54 52.25,29.54
VREG_S3C_0P752 on INNER LAYER 3 (solid shape): 52.01,29.3 52.07,29.24 52.15,29.2 52.17,29.2 52.26,29.07 52.28,29.04 52.3,29.02 52.3,28.82 52.25,28.69 52.3,28.56 52.3,28.31 52.25,28.17 52.3,28.03 52.3,27.95 52.46,27.79 52.51,27.76 52.56,27.73 52.56,27.65 52.4,27.6 52.25,27.43 52.08,27.42 51.96,27.5 51.93,27.51 51.9,27.54 51.81,27.61 51.78,27.67 51.8,27.7 51.89,27.93 51.79,28.14 51.77,28.16 51.77,28.23 51.79,28.24 51.87,28.43 51.79,28.62 51.77,28.64 51.77,28.72 51.88,28.93 51.77,29.14 51.77,29.22 51.85,29.3
VREG_S3C_0P752 on INNER LAYER 5 (solid shape): outline of 129 points within 51.52,27.72 53.38,29.94
VREG_S3C_0P752 on INNER LAYER 7 (solid shape): outline of 271 points within 51.49,26.96 53.65,29.59
VREG_S3C_0P752 on INNER LAYER 8 (solid shape): 52.42,30.65 52.84,30.28 52.84,29.48 52.84,29.44 52.84,29.4 52.79,29.28 52.6,29.22 52.49,29.25 52.47,29.36 52.48,29.54 52.37,29.68 52.35,29.7 52.35,29.82 52.12,30.05 51.9,29.82 51.9,29.47 51.97,29.4 51.97,29.39 52.01,29.31 52.07,29.24 52.11,29.14 52.04,29.06 51.88,29.02 51.8,29.12 51.74,29.16 51.5,29.4 51.5,29.71 51.42,29.79 50.18,29.79 49.73,29.34 49.24,29.34 48.92,29.66 48.92,29.91 49.26,30.25 49.34,30.25 49.36,30.24 49.46,30.2 49.57,30.24 49.58,30.25 49.73,30.35 50.86,30.33 50.88,30.33 51.08,30.3 51.23,30.43 51.24,30.43 51.31,30.51 51.76,30.67
VREG_S3C_0P752 on INNER LAYER 8 (solid shape): outline of 83 points within 51.6,27.74 53.46,29.72
VREG_S3C_0P752 on INNER LAYER 9 (solid shape): 52.43,30.37 52.55,30.36 52.74,30.32 52.78,30.01 52.79,29.83 52.85,29.76 52.9,29.53 52.86,28.59 53.16,28.26 53.15,28.06 53.07,28.02 52.66,28.01 52.56,28.01 51.8,28.05 51.28,28.22 50.66,28.23 49.76,28.23 49.73,28.2 48.56,28.2 48.33,28.43 48.33,29.28 48.66,30.05 49.64,30.22 49.72,30.23 49.8,30.21 49.84,30.14 49.84,29.8 49.57,29.53 49.57,29.26 49.71,29.11 50.81,29.11 50.9,29.03 50.9,29.02 50.94,28.96 50.99,28.91 51.01,28.9 51.01,28.79 51.07,28.72 51.11,28.69 51.3,28.49 51.59,28.49 51.7,28.61 51.7,28.98 51.76,29.03 52.06,29.03 52.37,29.35 52.37,29.94 52.29,30.03 52.22,30.03 52.21,30.03 52.12,30.05 52.04,30.03 52.03,30.03 51.94,30.03 51.88,29.96 51.88,29.71 51.83,29.67 51.51,29.67 51.4,29.78 50.55,29.78 50.49,29.83 50.49,30.39 50.59,30.57 51.08,30.6 51.22,30.58 52.14,30.62
VREG_S4A_2P04 on TOP (solid shape): 68.85,32.54 68.48,32.08 68.47,31.25 68.47,30.56 66.71,30.56 66.71,31.43 67.2,31.92 67.2,32.95 68.84,32.96
VREG_S4A_2P04 on INNER LAYER 3 (solid shape): 70.08,34.12 70.15,34.1 70.22,34.12 70.23,34.12 70.6,34.12 70.77,34.06 70.94,34.12 72.55,34.12 73.5,33.17 73.5,32.43 73.45,32.37 73.45,32.11 73.51,31.96 73.65,31.89 73.67,31.88 73.8,31.75 74.07,31.75 74.09,31.73 74.23,31.64 74.4,31.7 74.44,31.74 74.81,31.37 74.81,30.59 74.39,30.17 73.71,30.17 73.6,30.28 73.87,30.55 73.87,30.93 73.48,30.93 73.3,30.75 73.29,30.75 73.17,30.61 73.16,30.43 73.14,30.34 73.06,30.3 72.36,30.3 72.36,30.61 72.68,30.92 72.7,30.93 72.89,31.09 72.8,31.33 72.8,32.27 72.21,32.86 70.8,32.86 70.32,33.34 69.93,33.34 69.84,33.43 69.7,33.47 69.47,33.47 69.34,33.34 69.3,33.34 68.77,32.81 68.77,32.28 68.67,32.18 67.4,32.18 67.27,32.31 67.27,32.32 67.17,32.42 67.17,32.47 68.82,34.12 70.07,34.12
VREG_S5A_1P0_VIN_GR2 on TOP (solid shape): 66.38,30.56 64.41,30.56 64.35,31.06 63.63,31.69 63.76,32.11 64.41,32.84 66.38,32.84
VREG_S5A_1P0_VIN_GR2 on INNER LAYER 3 (solid shape): 66.33,32.86 66.33,32.02 65.88,31.57 65.1,31.57 64.67,32 64.67,32.64 65.29,33.26 65.93,33.26
VREG_S6A_1P35 on TOP (solid shape): 64.73,27.77 65.6,27.77 65.9,27.47 65.9,26.85 65.63,26.58 64.4,26.58 64.15,26.83 63.02,26.83 63.02,28.36 63.1,28.44 64.06,28.44
VREG_SD_3P3 on BOTTOM (solid shape): 74.6,23.37 74.4,23.17 74.4,22.52 74.35,22.47 73.85,22.47 73.65,22.67 73.65,22.97 73.8,23.12 73.8,23.77 74.6,23.77
VREG_SD_3P3 on INNER LAYER 8 (solid shape): outline of 548 points within 73.59,21.47 79.05,31.26
VREG_WL_3P3 on BOTTOM (solid shape): 22.69,15.54 22.69,14.52 22.7,13.97 22.65,13.92 22.4,13.57 22.15,13.32 21.75,13.22 21.5,13.27 21.5,13.97 21.9,14.07 22.05,14.22 22.05,14.67 21.99,15.52 22.02,15.55 22.68,15.55
N13736313 on INNER LAYER 2 (solid shape): 73.94,24.08 73.95,24.07 73.99,23.99 74.06,23.95 74.08,23.95 74.25,23.77 74.28,23.73 74.43,23.6 74.88,23.17 74.88,22.6 75.69,21.91 75.7,21.16 75.6,21.06 75.09,21.06 74.9,21.25 74.32,22.02 74.12,22.36 74.12,22.81 74.1,23.18 74.02,23.34 74,23.38 73.98,23.41 73.73,23.66 73.59,23.72 73.45,23.65 73.22,23.65 72.95,23.92 72.95,24.08 73.09,24.22 73.81,24.22
N13747022 on TOP (solid shape): 66.82,24.46 66.57,24.21 66.57,23.06 66.31,22.81 66.31,22.55 65.43,22.55 65.43,24.08 65.74,24.4 66,24.4 66.31,24.71 66.82,24.71
N13747238 on TOP (solid shape): 68.39,22.78 68.94,22.8 69.01,22.78 69.04,22.7 69.04,22.59 68.24,21.79 68.24,21.75 68.03,21.54 67.41,21.54 67.4,21.56 67.17,21.56 67.17,21.56 66.22,21.56 65.91,21.26 64.38,21.26 64.26,21.38 64.26,22.32 64.44,22.5 65.35,22.5 65.35,22.47 66.46,22.47 66.61,22.47 66.75,22.48 66.76,22.5 67.75,22.5 67.87,22.53 68.08,22.64 68.17,22.64 68.33,22.81
N13747238 on INNER LAYER 2 (solid shape): 69.31,24.06 69.31,23.95 69.29,23.93 69.23,23.89 69.2,23.82 69.2,23.81 69.13,23.74 69.12,23.74 68.99,23.68 68.93,23.55 68.93,23.53 68.68,23.29 68.16,23.29 68.11,23.3 68.05,23.29 67.91,23.29 67.86,23.3 67.81,23.29 67.09,23.29 66.95,23.15 66.95,23 66.95,22.73 66.95,22.72 66.95,22.17 66.56,21.78 65.92,21.78 65.91,21.82 65.76,21.95 65.57,21.9 65.49,21.86 65.42,21.89 65.34,21.97 65.34,22.33 65.56,22.55 66.4,22.55 66.48,22.63 66.48,23.91 66.58,24.01 66.69,24.01 66.71,23.99 66.87,23.9 67.04,23.99 67.05,24.01 67.3,24.01 67.42,23.91 67.58,23.91 67.59,23.91 67.96,23.91 68.03,23.93 68.09,23.96 68.11,23.96 68.91,23.96 68.98,24.04 69.05,24.08 69.09,24.12 69.25,24.12
N13747596 on TOP (solid shape): 68.47,28.84 69.05,28.27 69.05,27.7 68.79,27.7 68.79,27.83 68.16,28.46 66.89,28.46 66.76,28.59 66.76,29.79 68.47,29.79
N13747596 on INNER LAYER 2 (solid shape): 68.48,29.34 68.48,28.82 68.72,28.58 68.72,27.57 68.91,27.38 68.97,27.38 69.26,27.09 69.26,26.85 69.26,26.85 69.01,26.85 68.17,27.68 68.17,28.24 67.76,28.65 67.75,28.65 67.73,28.67 67.73,29.37 67.86,29.5 68.32,29.5
N13747700 on TOP (solid shape): 66.51,29.67 66.51,28.52 66.56,28.47 66.56,28 67.01,27.55 67.01,27.38 66.43,27.41 65.99,27.82 65.76,28.51 64.73,28.52 64.6,28.65 64.6,29.79 66.38,29.79
N13747828 on TOP (solid shape): 66.76,25.1 66.76,24.9 66.31,24.9 66,24.59 64.22,24.59 64.22,25.6 66.25,25.6
N13750716 on BOTTOM (solid shape): 30.55,23.71 30.55,23.43 30.27,23.15 30.27,23.17 29.23,22.12 28.04,22.12 28.04,23.27 29.71,23.27 30.25,23.81 30.44,23.81
N13750716 on INNER LAYER 9 (solid shape): 30.2,24.69 30.24,24.65 30.26,24.64 30.31,24.62 30.38,24.55 30.38,24.54 30.4,24.48 30.44,24.42 30.46,24.41 30.46,24.39 30.41,24.26 30.38,24.18 30.36,24.1 30.36,24.08 30.34,24.07 30.34,23.33 30.06,22.96 29.86,22.71 29.76,22.66 29.66,22.71 29.58,22.79 29.58,23.38 29.81,23.71 29.76,24.51 30,24.69
N13750716 on INNER LAYER 9: 30.31,24.62 30.38,24.55 30.38,24.54 30.41,24.46 30.46,24.4 30.41,24.26 30.36,24.06 30.41,23.86 30.41,23.66 30.36,23.36 30.06,22.96 29.86,22.71 29.76,22.66 29.66,22.71 29.58,22.79 29.58,23.38 29.81,23.71 29.76,24.51 29.97,24.66 30,24.69 30.2,24.69 30.24,24.65 30.3,24.63
N13750828 on BOTTOM (solid shape): 30.41,28.01 30.41,26.86 30.42,26.79 30.21,26.79 29.91,27.11 29.66,27.36 29.46,27.66 29.46,27.76 29.74,28.24 30.36,28.24
N13750828 on INNER LAYER 9 (solid shape): 30.43,28.01 30.41,26.7 30.36,26.6 30.36,26.31 30.16,25.96 30.09,25.94 29.5,26.52 29.5,28.2 30.24,28.2
N13750950 on BOTTOM (solid shape): 32.17,27.53 31.44,26.81 31.23,26.81 31.23,27.53 31.39,27.7 31.39,28.04 31.59,28.24 32.17,28.24
N13750950 on INNER LAYER 9 (solid shape): 31.86,27.76 31.86,27.31 31.8,27.24 31.8,27.19 31.52,26.91 31.52,26.74 31.46,26.67 31.4,26.56 31.42,26.44 31.43,26.43 31.44,26.36 31.44,26.23 31.43,26.22 31.43,26.15 31.39,26.06 31.3,25.96 31.29,25.96 31.23,25.93 31.18,25.89 31.04,25.89 30.93,26 30.93,26.09 31.16,26.32 31.16,26.34 31.18,26.36 31.18,27.84 31.25,27.91 31.71,27.91
N13751070 on BOTTOM (solid shape): 31.55,23.71 31.55,23.62 32.09,23.04 32.74,22.98 32.86,22.74 32.9,22.43 32.81,22.26 32.11,22.21 31.76,22.61 31.66,22.86 31.26,23.26 31.18,23.67 31.18,23.67 31.18,23.75 31.24,23.81 31.45,23.81
N13751070 on INNER LAYER 9 (solid shape): 31.42,24.39 31.42,24.19 31.41,24.18 31.37,24.04 31.43,23.91 31.43,23.74 32.04,23.09 32.04,22.81 32.01,22.76 31.86,22.71 31.76,22.71 31.16,23.26 31.11,23.46 31.16,23.76 31.16,24.26 31.11,24.31 30.9,24.55 31.01,24.66 31.15,24.66
N13773151 on BOTTOM (solid shape): 74.51,44.22 74.51,43.05 74.91,42.65 75.11,42.65 75.19,42.57 75.19,41.96 74.75,41.52 74.6,41.52 74.59,41.51 74.59,39.95 74.93,39.61 74.93,38.67 73.99,38.67 73.82,38.84 73.82,39.48 73.54,39.76 72.53,39.76 72.48,39.81 72.48,43.94 72.91,44.37 74.36,44.37
N13778471 on BOTTOM (solid shape): 40.42,41.36 41.4,41.36 41.54,41.5 41.95,41.5 42.09,41.36 42.09,39.23 41.8,38.94 40.42,38.94 38.68,40.68 38.68,41.88 39.9,41.88
N13780517 on BOTTOM (solid shape): 43.48,36.73 42.31,35.56 42.31,33.05 41.86,32.6 40.94,32.6 40.49,33.05 40.49,36.31 41.79,37.61 43.48,37.61
N13780655 on INNER LAYER 9 (solid shape): 2.85,41.37 1.97,41.37 1.97,42.64 2.85,42.64
N13781141 on INNER LAYER 9 (solid shape): 2.95,30 2.95,28.91 2.12,28.91 2.07,28.96 2.07,30.08 2.12,30.13 2.82,30.13
N13893733 on BOTTOM (solid shape): 78.59,47.66 78.59,39.88 78.05,39.34 78.05,39.36 77.83,39.14 75.93,39.14 75.84,39.23 75.84,40.58 76.11,40.85 76.44,40.85 77.32,41.74 77.31,42.79 76.54,43.8 76.57,47.73 76.6,48.01 78.24,48.01
N14211485 on BOTTOM (solid shape): 52.36,34.64 53.27,34.42 53.67,34.12 54,33.14 53.88,32.15 52.72,32.17 52.27,33.16 51.8,33.59 50.77,33.85 50.65,33.97 48.8,33.97 48.74,34.03 48.74,34.64 51.05,34.67
